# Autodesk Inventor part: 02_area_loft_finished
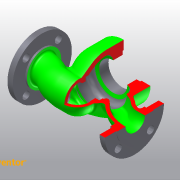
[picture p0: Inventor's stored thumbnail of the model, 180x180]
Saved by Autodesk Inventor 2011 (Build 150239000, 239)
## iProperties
Company: Autodesk
Created: 2007-01
Part Number: 02_area_loft_finished
Document SubType Name: Modeling
Designer: Lieven Grauls
Stock Number: 02_area_loft_finished
Project: Valve Techcamp 2008
Density: 1 g/cm^3
Author: Lieven Grauls
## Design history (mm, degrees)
node "02_are_loft_def_finished" dims "d0" = 10
feature "Sculpt1"
fillet "Fillet1" dims "d1" = 8
fillet "Fillet2" dims "d2" = 8, "d11" = 5
revolve "Revolution1" stored, may be unused: angle "d4" = 90 deg
revolve "Revolution2" stored, may be unused: angle "d10" = 90 deg
sketch "Sketch5" dims "d25" = 120
  geometry: L1 (0, 0)-(-42.426, 42.426); L2 (0, 137.1)-(0, -122.6) reference; C1 r 77.5 at (0, 0) reference; 1 further point
  constraints: 2 coincident, 2 end point, 3 other
  dimensions: "d24" = 45 deg angle of L1 L2
hole "Hole2" sketch "Sketch5" at (-42.426, 42.426) diameter "d26" = 19; stored, may be unused: countersink angle "d30" = 90 deg, drill point angle "d32" = 118 deg; dims "d27" = 6, "d28" = 4, "d29" = 2, "d31" = 8
pattern_circular "Circular Pattern2" dims angle "d34" = 360 deg
mirror "Mirror1"
sketch "Sketch6" dims "d37" = 112
  geometry: L1 (0, 0)-(21.43, 51.737); L2 (0, 119.7)-(0, -119.7) reference; C1 r 70 at (0, 0) reference
  constraints: 2 end point, 1 coincident, 3 other
  dimensions: "d36" = 22.5 deg angle of L1 L2
hole "Hole3" sketch "Sketch6" at (21.43, 51.737) diameter "d38" = 10.592; stored, may be unused: countersink angle "d42" = 90 deg, drill point angle "d44" = 118 deg; dims "d39" = 14, "d40" = 4, "d41" = 2, "d43" = 18
pattern_circular "Circular Pattern3" dims angle "d46" = 360 deg
sketch "Sketch7"
  geometry: L1 (0, 0)-(-189.613, 0); L2 (-189.613, 0)-(-189.613, 104.83); L3 (-189.613, 104.83)-(0, 104.83); L4 (0, 104.83)-(0, 0)
  constraints: 8 end point, 2 parallel, 1 horizontal, 1 perpendicular
extrude "Extrusion1" cut sketch "Sketch7" stored distance "d48" = 10; taper "d49" = 0 deg
node "Volumenkörper1"
node "Volumenkörpern"
node "Oberflächenkörpern"
feature "Derived Work Body1"
node "Flächen1"
sketch "Sketch15"
  geometry: L1 (-80, 100)-(-46.5, 100); L2 (-37.013, 96.7)-(-37.013, 60); L3 (-37.013, 60)-(-35.513, 60); L4 (-80, 113)-(-80, 100); L5 (-46.5, 100)-(-46.5, 96.7); L6 (-46.5, 96.7)-(-37.013, 96.7); L7 (0, -22.6)-(0, 135.6); L8 (-96, 0)-(16, 0); L9 (-35.513, 60)-(-35.513, 0); L10 (-35.513, 0)-(0, 0)
  constraints: 20 end point
workplane "Work Plane6"
feature "RevolutionSrf2"
node "Flächen2"
feature "RevolutionSrf3"
node "Flächen3"
feature "OffsetSrf2" [RevolutionSrf]
node "Flächen4"
feature "RevolutionSrf1"
node "Flächen5"
feature "OffsetSrf1" [RevolutionSrf]
node "Flächen6"
sketch "Sketch20"
  geometry: L1 (0, -81.107)-(0, 145.351); L2 (-205.8, 0)-(205.8, 0); L3 (-130, 0)-(-152.983, 0); L4 (-128, 77.5)-(-114, 77.5); L5 (-114, 77.5)-(-114, 45); L6 (-114, 45)-(-107, 45); L7 (-107, 45)-(-107, 100.638); L8 (-128, 77.5)-(-128, 48); L9 (-128, 48)-(-130, 48); L10 (-130, 48)-(-130, 0)
  constraints: 20 end point
feature "DerivedBody::02_are_loft_def_finished"
other parameters: "d3" = 90 deg, "d9" = 90 deg
